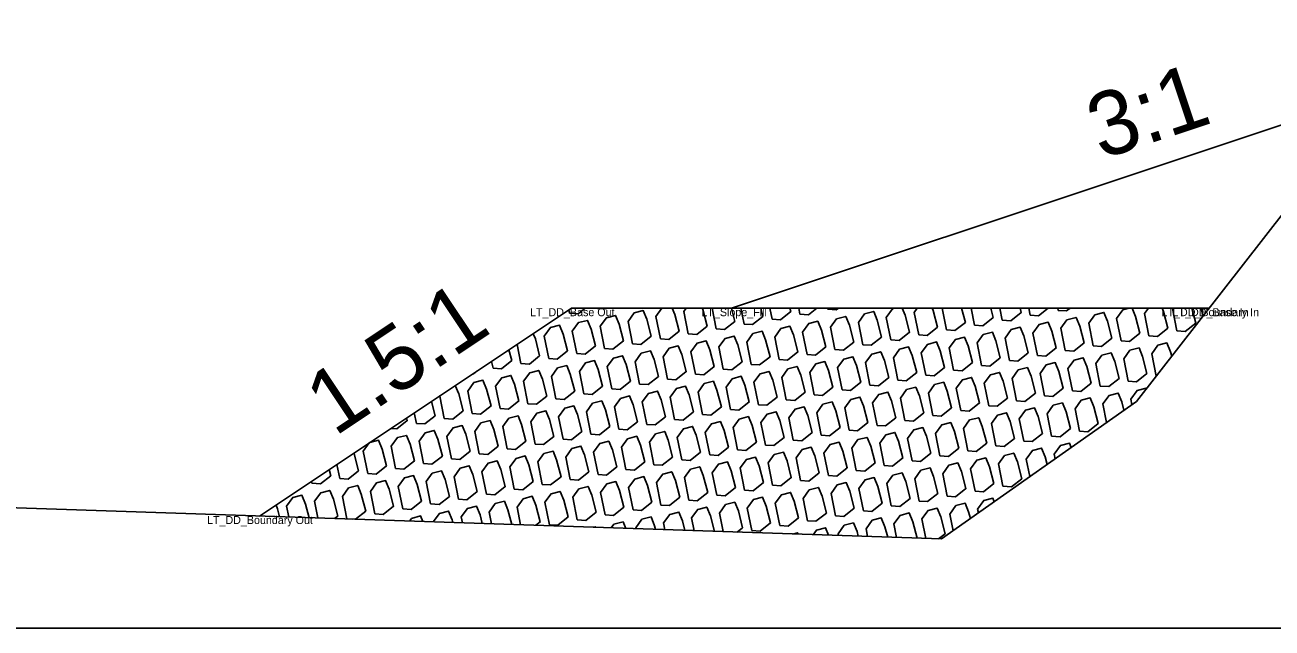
# Model space of a CAD drawing. Extents: x -26 to 203, y -10 to 20020.
# Drawn here: x 60.55 to 76.13, y 15500 to 15507.54 of the extents above; entities that cross this region are included whole.
import ezdxf

# ---------------------------------------------------------------- set-up
doc = ezdxf.new("R2010")
doc.units = 0
for name, color, linetype in [('Default', 7, 'Continuous'), ('Exist Cross Section Cell', 7, 'Continuous'), ('Exist XS Ground Line', 7, 'Continuous'), ('Old_Level_1', 7, 'Continuous'), ('Prop CMT Rip Rap Class II', 7, 'Continuous'), ('Prop CMT Slope Grass', 7, 'Continuous'), ('Prop XS Side Slope Text', 7, 'Continuous')]:
    doc.layers.add(name, color=color, linetype=linetype)

msp = doc.modelspace()

# ---------------------------------------------------------------- linework, layer by layer
at = {"layer": 'Exist Cross Section Cell'}
msp.add_line((0, 15500), (100, 15500), dxfattribs=at)
at = {"layer": 'Exist XS Ground Line'}
for p, q in [((74.431, 15502.834), (76.297, 15505.23)), ((71.996, 15501.114), (74.431, 15502.834)), ((57.187, 15501.614), (71.996, 15501.114))]:
    msp.add_line(p, q, dxfattribs=at)
at = {"layer": 'Old_Level_1'}
for p, q in [((67.341, 15503.979), (67.35, 15503.937)), ((67.698, 15504), (67.698, 15503.998)), ((69.13, 15504), (69.182, 15503.74)), ((69.491, 15504), (69.53, 15503.801)), ((69.852, 15504), (69.879, 15503.863)), ((70.212, 15504), (70.227, 15503.924)), ((70.573, 15504), (70.576, 15503.986)), ((72.005, 15504), (72.059, 15503.728)), ((72.366, 15504), (72.408, 15503.789)), ((72.727, 15504), (72.756, 15503.851)), ((73.088, 15504), (73.105, 15503.912)), ((73.448, 15504), (73.454, 15503.973)), ((75.241, 15504), (75.261, 15503.9)), ((66.694, 15503.548), (66.741, 15503.31)), ((66.376, 15503.335), (66.393, 15503.248)), ((65.41, 15502.691), (65.436, 15502.56)), ((64.444, 15502.047), (64.479, 15501.871)), ((64.125, 15501.835), (64.13, 15501.81)), ((63.478, 15501.403), (63.479, 15501.401)), ((64.568, 15501.367), (64.637, 15501.362))]:
    msp.add_line(p, q, dxfattribs=at)
for points in [[(67.35, 15503.937), (67.455, 15503.929), (67.544, 15504)], [(67.698, 15503.998), (67.804, 15503.99), (67.816, 15504)], [(68.503, 15504), (68.429, 15503.897), (68.484, 15503.617)], [(68.484, 15503.617), (68.59, 15503.609), (68.719, 15503.713), (68.665, 15503.923), (68.633, 15504)], [(68.807, 15504), (68.777, 15503.958), (68.833, 15503.678)], [(68.833, 15503.678), (68.938, 15503.671), (69.068, 15503.774), (69.013, 15503.985), (69.007, 15504)], [(69.182, 15503.74), (69.287, 15503.732), (69.416, 15503.835), (69.374, 15504)], [(69.53, 15503.801), (69.635, 15503.794), (69.765, 15503.897), (69.738, 15504)], [(69.879, 15503.863), (69.984, 15503.855), (70.114, 15503.958), (70.103, 15504)], [(70.227, 15503.924), (70.333, 15503.917), (70.437, 15504)], [(70.576, 15503.986), (70.681, 15503.978), (70.709, 15504)], [(71.418, 15504), (71.383, 15503.991), (71.306, 15503.885), (71.362, 15503.605)], [(71.362, 15503.605), (71.467, 15503.597), (71.597, 15503.7), (71.542, 15503.911), (71.506, 15504)], [(71.694, 15504), (71.655, 15503.946), (71.711, 15503.666)], [(71.711, 15503.666), (71.816, 15503.658), (71.945, 15503.762), (71.891, 15503.972), (71.88, 15504)], [(72.059, 15503.728), (72.164, 15503.72), (72.294, 15503.823), (72.248, 15504)], [(72.408, 15503.789), (72.513, 15503.781), (72.643, 15503.885), (72.613, 15504)], [(72.756, 15503.851), (72.862, 15503.843), (72.991, 15503.946), (72.977, 15504)], [(73.105, 15503.912), (73.21, 15503.904), (73.33, 15504)], [(73.454, 15503.973), (73.559, 15503.966), (73.602, 15504)], [(74.343, 15504), (74.261, 15503.979), (74.184, 15503.872), (74.24, 15503.592)], [(74.24, 15503.592), (74.345, 15503.585), (74.474, 15503.688), (74.42, 15503.898), (74.378, 15504)], [(74.581, 15504), (74.533, 15503.934), (74.588, 15503.654)], [(74.588, 15503.654), (74.694, 15503.646), (74.823, 15503.749), (74.769, 15503.96), (74.752, 15504)], [(74.885, 15504), (74.881, 15503.995), (74.937, 15503.715)], [(74.937, 15503.715), (75.042, 15503.708), (75.172, 15503.811), (75.123, 15504)], [(66.741, 15503.31), (66.847, 15503.302), (66.976, 15503.405), (66.922, 15503.616), (66.895, 15503.681)], [(74.872, 15503.401), (74.858, 15503.456), (74.812, 15503.566), (74.699, 15503.536), (74.622, 15503.43), (74.677, 15503.15)], [(66.393, 15503.248), (66.498, 15503.241), (66.628, 15503.344), (66.592, 15503.48)], [(66.142, 15503.18), (66.149, 15503.179), (66.19, 15503.212)], [(65.784, 15502.621), (65.89, 15502.614), (66.019, 15502.717), (65.965, 15502.927), (65.922, 15503.032)], [(74.276, 15502.725), (74.249, 15502.829), (74.204, 15502.939), (74.09, 15502.909), (74.013, 15502.803), (74.059, 15502.572)], [(74.555, 15502.994), (74.553, 15503), (74.439, 15502.971), (74.362, 15502.864), (74.375, 15502.795)], [(65.436, 15502.56), (65.541, 15502.552), (65.671, 15502.655), (65.624, 15502.834)], [(65.733, 15502.907), (65.729, 15502.901), (65.784, 15502.621)], [(65.117, 15502.496), (65.193, 15502.491), (65.322, 15502.594), (65.313, 15502.627)], [(64.847, 15502.316), (64.772, 15502.213), (64.828, 15501.933)], [(64.828, 15501.933), (64.933, 15501.925), (65.062, 15502.028), (65.008, 15502.239), (64.963, 15502.349), (64.853, 15502.32)], [(73.617, 15502.259), (73.596, 15502.312), (73.482, 15502.282), (73.405, 15502.176), (73.416, 15502.118)], [(64.479, 15501.871), (64.584, 15501.864), (64.714, 15501.967), (64.659, 15502.177), (64.655, 15502.188)], [(73.316, 15502.047), (73.292, 15502.14), (73.247, 15502.25), (73.133, 15502.221), (73.056, 15502.114), (73.1, 15501.894)], [(64.13, 15501.81), (64.236, 15501.802), (64.365, 15501.905), (64.345, 15501.982)], [(64.414, 15501.37), (64.454, 15501.401), (64.4, 15501.612), (64.354, 15501.722), (64.241, 15501.692), (64.164, 15501.586), (64.205, 15501.377)], [(64.675, 15501.361), (64.803, 15501.463), (64.748, 15501.673), (64.703, 15501.783), (64.589, 15501.754), (64.512, 15501.647), (64.568, 15501.367)], [(63.727, 15501.393), (63.702, 15501.489), (63.682, 15501.539)], [(64.095, 15501.38), (64.051, 15501.55), (64.006, 15501.66), (63.892, 15501.631), (63.815, 15501.524), (63.842, 15501.389)], [(66.259, 15501.307), (66.231, 15501.415), (66.186, 15501.525), (66.073, 15501.495), (65.996, 15501.389), (66.01, 15501.316)], [(66.627, 15501.295), (66.58, 15501.477), (66.535, 15501.586), (66.421, 15501.557), (66.344, 15501.45), (66.373, 15501.303)], [(66.929, 15501.285), (66.983, 15501.327), (66.929, 15501.538), (66.884, 15501.648), (66.77, 15501.618), (66.693, 15501.512), (66.737, 15501.291)], [(69.159, 15501.209), (69.109, 15501.403), (69.064, 15501.512), (68.95, 15501.483), (68.873, 15501.377), (68.905, 15501.218)], [(69.444, 15501.2), (69.512, 15501.254), (69.458, 15501.464), (69.413, 15501.574), (69.299, 15501.545), (69.222, 15501.438), (69.268, 15501.206)], [(72.357, 15501.369), (72.335, 15501.452), (72.29, 15501.562), (72.176, 15501.532), (72.099, 15501.426), (72.141, 15501.216)], [(72.656, 15501.58), (72.639, 15501.623), (72.525, 15501.594), (72.448, 15501.487), (72.457, 15501.44)], [(65.518, 15501.332), (65.489, 15501.402), (65.375, 15501.372), (65.35, 15501.338)], [(65.892, 15501.32), (65.883, 15501.354), (65.838, 15501.463), (65.724, 15501.434), (65.647, 15501.328)], [(68.424, 15501.234), (68.412, 15501.28), (68.367, 15501.39), (68.253, 15501.36), (68.176, 15501.254), (68.178, 15501.242)], [(68.791, 15501.222), (68.761, 15501.341), (68.715, 15501.451), (68.602, 15501.422), (68.525, 15501.315), (68.541, 15501.23)], [(71.324, 15501.136), (71.29, 15501.268), (71.244, 15501.377), (71.131, 15501.348), (71.054, 15501.241), (71.073, 15501.145)], [(71.691, 15501.124), (71.638, 15501.329), (71.593, 15501.439), (71.479, 15501.409), (71.402, 15501.303), (71.436, 15501.132)], [(71.959, 15501.115), (72.041, 15501.18), (71.987, 15501.39), (71.942, 15501.5), (71.828, 15501.471), (71.751, 15501.364), (71.799, 15501.12)], [(67.672, 15501.26), (67.67, 15501.267), (67.646, 15501.26)], [(68.052, 15501.247), (68.018, 15501.328), (67.904, 15501.299), (67.871, 15501.253)], [(70.586, 15501.161), (70.547, 15501.254), (70.433, 15501.225), (70.392, 15501.168)], [(70.956, 15501.149), (70.941, 15501.206), (70.896, 15501.316), (70.782, 15501.286), (70.705, 15501.18), (70.71, 15501.157)], [(70.206, 15501.174), (70.199, 15501.193), (70.135, 15501.176)]]:
    msp.add_lwpolyline(points, dxfattribs=at)
for points in [[(67.439, 15503.433), (67.544, 15503.425), (67.673, 15503.528), (67.619, 15503.739), (67.574, 15503.848), (67.46, 15503.819), (67.383, 15503.713)], [(67.787, 15503.494), (67.892, 15503.486), (68.022, 15503.59), (67.968, 15503.8), (67.922, 15503.91), (67.809, 15503.88), (67.732, 15503.774)], [(68.136, 15503.556), (68.241, 15503.548), (68.371, 15503.651), (68.316, 15503.862), (68.271, 15503.971), (68.157, 15503.942), (68.08, 15503.835)], [(70.665, 15503.482), (70.77, 15503.474), (70.9, 15503.577), (70.845, 15503.788), (70.8, 15503.898), (70.686, 15503.868), (70.609, 15503.762)], [(71.013, 15503.543), (71.119, 15503.536), (71.248, 15503.639), (71.194, 15503.849), (71.149, 15503.959), (71.035, 15503.93), (70.958, 15503.823)], [(73.542, 15503.469), (73.648, 15503.462), (73.777, 15503.565), (73.723, 15503.776), (73.678, 15503.885), (73.564, 15503.856), (73.487, 15503.749)], [(73.891, 15503.531), (73.996, 15503.523), (74.126, 15503.626), (74.071, 15503.837), (74.026, 15503.947), (73.913, 15503.917), (73.835, 15503.811)], [(67.09, 15503.371), (67.195, 15503.363), (67.325, 15503.467), (67.27, 15503.677), (67.225, 15503.787), (67.111, 15503.758), (67.034, 15503.651)], [(69.619, 15503.297), (69.724, 15503.29), (69.854, 15503.393), (69.799, 15503.603), (69.754, 15503.713), (69.64, 15503.684), (69.563, 15503.577)], [(69.968, 15503.359), (70.073, 15503.351), (70.202, 15503.454), (70.148, 15503.665), (70.103, 15503.775), (69.989, 15503.745), (69.912, 15503.639)], [(70.316, 15503.42), (70.421, 15503.413), (70.551, 15503.516), (70.497, 15503.726), (70.451, 15503.836), (70.338, 15503.807), (70.261, 15503.7)], [(72.497, 15503.285), (72.602, 15503.277), (72.731, 15503.381), (72.677, 15503.591), (72.632, 15503.701), (72.518, 15503.671), (72.441, 15503.565)], [(72.845, 15503.346), (72.951, 15503.339), (73.08, 15503.442), (73.026, 15503.653), (72.98, 15503.762), (72.867, 15503.733), (72.79, 15503.626)], [(73.194, 15503.408), (73.299, 15503.4), (73.429, 15503.503), (73.374, 15503.714), (73.329, 15503.824), (73.215, 15503.794), (73.138, 15503.688)], [(68.922, 15503.174), (69.027, 15503.167), (69.157, 15503.27), (69.102, 15503.481), (69.057, 15503.59), (68.943, 15503.561), (68.866, 15503.454)], [(69.27, 15503.236), (69.376, 15503.228), (69.505, 15503.331), (69.451, 15503.542), (69.406, 15503.652), (69.292, 15503.622), (69.215, 15503.516)], [(71.799, 15503.162), (71.905, 15503.154), (72.034, 15503.258), (71.98, 15503.468), (71.935, 15503.578), (71.821, 15503.548), (71.744, 15503.442)], [(72.148, 15503.224), (72.253, 15503.216), (72.383, 15503.319), (72.328, 15503.53), (72.283, 15503.639), (72.17, 15503.61), (72.092, 15503.503)], [(67.876, 15502.99), (67.981, 15502.982), (68.111, 15503.086), (68.056, 15503.296), (68.011, 15503.406), (67.898, 15503.376), (67.82, 15503.27)], [(68.225, 15503.051), (68.33, 15503.044), (68.459, 15503.147), (68.405, 15503.358), (68.36, 15503.467), (68.246, 15503.438), (68.169, 15503.331)], [(68.573, 15503.113), (68.679, 15503.105), (68.808, 15503.208), (68.754, 15503.419), (68.708, 15503.529), (68.595, 15503.499), (68.518, 15503.393)], [(70.754, 15502.978), (70.859, 15502.97), (70.989, 15503.073), (70.934, 15503.284), (70.889, 15503.393), (70.775, 15503.364), (70.698, 15503.258)], [(71.102, 15503.039), (71.208, 15503.031), (71.337, 15503.135), (71.283, 15503.345), (71.238, 15503.455), (71.124, 15503.426), (71.047, 15503.319)], [(71.451, 15503.101), (71.556, 15503.093), (71.686, 15503.196), (71.631, 15503.407), (71.586, 15503.516), (71.472, 15503.487), (71.395, 15503.381)], [(73.631, 15502.965), (73.737, 15502.958), (73.866, 15503.061), (73.812, 15503.271), (73.767, 15503.381), (73.653, 15503.352), (73.576, 15503.245)], [(73.98, 15503.027), (74.085, 15503.019), (74.215, 15503.122), (74.16, 15503.333), (74.115, 15503.443), (74.001, 15503.413), (73.924, 15503.307)], [(74.329, 15503.088), (74.434, 15503.081), (74.563, 15503.184), (74.509, 15503.394), (74.464, 15503.504), (74.35, 15503.475), (74.273, 15503.368)], [(67.179, 15502.867), (67.284, 15502.859), (67.414, 15502.963), (67.359, 15503.173), (67.314, 15503.283), (67.2, 15503.253), (67.123, 15503.147)], [(67.527, 15502.928), (67.633, 15502.921), (67.762, 15503.024), (67.708, 15503.235), (67.663, 15503.344), (67.549, 15503.315), (67.472, 15503.208)], [(70.057, 15502.855), (70.162, 15502.847), (70.291, 15502.95), (70.237, 15503.161), (70.192, 15503.271), (70.078, 15503.241), (70.001, 15503.135)], [(70.405, 15502.916), (70.51, 15502.909), (70.64, 15503.012), (70.585, 15503.222), (70.54, 15503.332), (70.427, 15503.303), (70.35, 15503.196)], [(72.934, 15502.842), (73.039, 15502.835), (73.169, 15502.938), (73.115, 15503.149), (73.069, 15503.258), (72.956, 15503.229), (72.879, 15503.122)], [(73.283, 15502.904), (73.388, 15502.896), (73.518, 15502.999), (73.463, 15503.21), (73.418, 15503.32), (73.304, 15503.29), (73.227, 15503.184)], [(66.133, 15502.683), (66.238, 15502.675), (66.368, 15502.778), (66.313, 15502.989), (66.268, 15503.098), (66.155, 15503.069), (66.077, 15502.963)], [(66.482, 15502.744), (66.587, 15502.736), (66.716, 15502.84), (66.662, 15503.05), (66.617, 15503.16), (66.503, 15503.131), (66.426, 15503.024)], [(66.83, 15502.806), (66.936, 15502.798), (67.065, 15502.901), (67.011, 15503.112), (66.965, 15503.221), (66.852, 15503.192), (66.775, 15503.086)], [(69.011, 15502.67), (69.116, 15502.663), (69.246, 15502.766), (69.191, 15502.976), (69.146, 15503.086), (69.032, 15503.057), (68.955, 15502.95)], [(69.359, 15502.732), (69.465, 15502.724), (69.594, 15502.827), (69.54, 15503.038), (69.495, 15503.148), (69.381, 15503.118), (69.304, 15503.012)], [(69.708, 15502.793), (69.813, 15502.786), (69.943, 15502.889), (69.888, 15503.099), (69.843, 15503.209), (69.729, 15503.18), (69.652, 15503.073)], [(71.888, 15502.658), (71.994, 15502.65), (72.123, 15502.754), (72.069, 15502.964), (72.024, 15503.074), (71.91, 15503.044), (71.833, 15502.938)], [(72.237, 15502.719), (72.342, 15502.712), (72.472, 15502.815), (72.417, 15503.026), (72.372, 15503.135), (72.258, 15503.106), (72.181, 15502.999)], [(72.586, 15502.781), (72.691, 15502.773), (72.82, 15502.876), (72.766, 15503.087), (72.721, 15503.197), (72.607, 15503.167), (72.53, 15503.061)], [(68.314, 15502.547), (68.419, 15502.54), (68.548, 15502.643), (68.494, 15502.854), (68.449, 15502.963), (68.335, 15502.934), (68.258, 15502.827)], [(68.662, 15502.609), (68.767, 15502.601), (68.897, 15502.704), (68.842, 15502.915), (68.797, 15503.025), (68.684, 15502.995), (68.607, 15502.889)], [(71.191, 15502.535), (71.296, 15502.527), (71.426, 15502.631), (71.372, 15502.841), (71.326, 15502.951), (71.213, 15502.921), (71.136, 15502.815)], [(71.54, 15502.596), (71.645, 15502.589), (71.775, 15502.692), (71.72, 15502.903), (71.675, 15503.012), (71.561, 15502.983), (71.484, 15502.876)], [(67.268, 15502.363), (67.373, 15502.355), (67.503, 15502.459), (67.448, 15502.669), (67.403, 15502.779), (67.289, 15502.749), (67.212, 15502.643)], [(67.616, 15502.424), (67.722, 15502.417), (67.851, 15502.52), (67.797, 15502.731), (67.752, 15502.84), (67.638, 15502.811), (67.561, 15502.704)], [(67.965, 15502.486), (68.07, 15502.478), (68.2, 15502.581), (68.145, 15502.792), (68.1, 15502.902), (67.986, 15502.872), (67.909, 15502.766)], [(70.145, 15502.351), (70.251, 15502.343), (70.38, 15502.446), (70.326, 15502.657), (70.281, 15502.766), (70.167, 15502.737), (70.09, 15502.631)], [(70.494, 15502.412), (70.599, 15502.404), (70.729, 15502.508), (70.674, 15502.718), (70.629, 15502.828), (70.515, 15502.799), (70.438, 15502.692)], [(70.843, 15502.474), (70.948, 15502.466), (71.077, 15502.569), (71.023, 15502.78), (70.978, 15502.889), (70.864, 15502.86), (70.787, 15502.754)], [(73.372, 15502.4), (73.477, 15502.392), (73.606, 15502.495), (73.552, 15502.706), (73.507, 15502.816), (73.393, 15502.786), (73.316, 15502.68)], [(73.72, 15502.461), (73.826, 15502.454), (73.955, 15502.557), (73.901, 15502.767), (73.855, 15502.877), (73.742, 15502.848), (73.665, 15502.741)], [(66.571, 15502.24), (66.676, 15502.232), (66.805, 15502.336), (66.751, 15502.546), (66.706, 15502.656), (66.592, 15502.626), (66.515, 15502.52)], [(66.919, 15502.301), (67.024, 15502.294), (67.154, 15502.397), (67.1, 15502.608), (67.054, 15502.717), (66.941, 15502.688), (66.864, 15502.581)], [(69.448, 15502.228), (69.553, 15502.22), (69.683, 15502.323), (69.629, 15502.534), (69.583, 15502.644), (69.47, 15502.614), (69.393, 15502.508)], [(69.797, 15502.289), (69.902, 15502.282), (70.032, 15502.385), (69.977, 15502.595), (69.932, 15502.705), (69.818, 15502.676), (69.741, 15502.569)], [(72.326, 15502.215), (72.431, 15502.208), (72.561, 15502.311), (72.506, 15502.522), (72.461, 15502.631), (72.347, 15502.602), (72.27, 15502.495)], [(72.674, 15502.277), (72.78, 15502.269), (72.909, 15502.372), (72.855, 15502.583), (72.81, 15502.693), (72.696, 15502.663), (72.619, 15502.557)], [(73.023, 15502.338), (73.128, 15502.331), (73.258, 15502.434), (73.203, 15502.644), (73.158, 15502.754), (73.045, 15502.725), (72.967, 15502.618)], [(65.525, 15502.056), (65.63, 15502.048), (65.76, 15502.151), (65.705, 15502.362), (65.66, 15502.471), (65.546, 15502.442), (65.469, 15502.336)], [(65.873, 15502.117), (65.979, 15502.109), (66.108, 15502.213), (66.054, 15502.423), (66.009, 15502.533), (65.895, 15502.504), (65.818, 15502.397)], [(66.222, 15502.179), (66.327, 15502.171), (66.457, 15502.274), (66.402, 15502.485), (66.357, 15502.594), (66.243, 15502.565), (66.166, 15502.459)], [(68.402, 15502.043), (68.508, 15502.036), (68.637, 15502.139), (68.583, 15502.349), (68.538, 15502.459), (68.424, 15502.43), (68.347, 15502.323)], [(68.751, 15502.105), (68.856, 15502.097), (68.986, 15502.2), (68.931, 15502.411), (68.886, 15502.521), (68.772, 15502.491), (68.695, 15502.385)], [(69.1, 15502.166), (69.205, 15502.159), (69.334, 15502.262), (69.28, 15502.472), (69.235, 15502.582), (69.121, 15502.553), (69.044, 15502.446)], [(71.28, 15502.031), (71.385, 15502.023), (71.515, 15502.127), (71.46, 15502.337), (71.415, 15502.447), (71.302, 15502.417), (71.224, 15502.311)], [(71.629, 15502.092), (71.734, 15502.085), (71.863, 15502.188), (71.809, 15502.399), (71.764, 15502.508), (71.65, 15502.479), (71.573, 15502.372)], [(71.977, 15502.154), (72.083, 15502.146), (72.212, 15502.249), (72.158, 15502.46), (72.112, 15502.57), (71.999, 15502.54), (71.922, 15502.434)], [(65.176, 15501.994), (65.281, 15501.987), (65.411, 15502.09), (65.357, 15502.3), (65.311, 15502.41), (65.198, 15502.381), (65.121, 15502.274)], [(67.705, 15501.92), (67.81, 15501.913), (67.94, 15502.016), (67.886, 15502.227), (67.84, 15502.336), (67.727, 15502.307), (67.65, 15502.2)], [(68.054, 15501.982), (68.159, 15501.974), (68.289, 15502.077), (68.234, 15502.288), (68.189, 15502.398), (68.075, 15502.368), (67.998, 15502.262)], [(70.583, 15501.908), (70.688, 15501.9), (70.818, 15502.004), (70.763, 15502.214), (70.718, 15502.324), (70.604, 15502.294), (70.527, 15502.188)], [(70.931, 15501.969), (71.037, 15501.962), (71.166, 15502.065), (71.112, 15502.276), (71.067, 15502.385), (70.953, 15502.356), (70.876, 15502.249)], [(66.659, 15501.736), (66.765, 15501.728), (66.894, 15501.832), (66.84, 15502.042), (66.795, 15502.152), (66.681, 15502.122), (66.604, 15502.016)], [(67.008, 15501.797), (67.113, 15501.79), (67.243, 15501.893), (67.188, 15502.104), (67.143, 15502.213), (67.029, 15502.184), (66.952, 15502.077)], [(67.357, 15501.859), (67.462, 15501.851), (67.591, 15501.954), (67.537, 15502.165), (67.492, 15502.275), (67.378, 15502.245), (67.301, 15502.139)], [(69.537, 15501.724), (69.642, 15501.716), (69.772, 15501.819), (69.717, 15502.03), (69.672, 15502.139), (69.559, 15502.11), (69.481, 15502.004)], [(69.886, 15501.785), (69.991, 15501.777), (70.12, 15501.881), (70.066, 15502.091), (70.021, 15502.201), (69.907, 15502.172), (69.83, 15502.065)], [(70.234, 15501.847), (70.34, 15501.839), (70.469, 15501.942), (70.415, 15502.153), (70.369, 15502.262), (70.256, 15502.233), (70.179, 15502.127)], [(72.763, 15501.773), (72.869, 15501.765), (72.998, 15501.868), (72.944, 15502.079), (72.899, 15502.189), (72.785, 15502.159), (72.708, 15502.053)], [(65.962, 15501.613), (66.067, 15501.605), (66.197, 15501.709), (66.143, 15501.919), (66.097, 15502.029), (65.984, 15501.999), (65.907, 15501.893)], [(66.311, 15501.674), (66.416, 15501.667), (66.546, 15501.77), (66.491, 15501.981), (66.446, 15502.09), (66.332, 15502.061), (66.255, 15501.954)], [(68.84, 15501.601), (68.945, 15501.593), (69.075, 15501.696), (69.02, 15501.907), (68.975, 15502.017), (68.861, 15501.987), (68.784, 15501.881)], [(69.188, 15501.662), (69.294, 15501.655), (69.423, 15501.758), (69.369, 15501.968), (69.324, 15502.078), (69.21, 15502.049), (69.133, 15501.942)], [(71.718, 15501.588), (71.823, 15501.581), (71.952, 15501.684), (71.898, 15501.895), (71.853, 15502.004), (71.739, 15501.975), (71.662, 15501.868)], [(72.066, 15501.65), (72.171, 15501.642), (72.301, 15501.745), (72.246, 15501.956), (72.201, 15502.066), (72.088, 15502.036), (72.011, 15501.93)], [(72.415, 15501.711), (72.52, 15501.704), (72.65, 15501.807), (72.595, 15502.017), (72.55, 15502.127), (72.436, 15502.098), (72.359, 15501.991)], [(64.916, 15501.429), (65.022, 15501.421), (65.151, 15501.524), (65.097, 15501.735), (65.052, 15501.844), (64.938, 15501.815), (64.861, 15501.709)], [(65.265, 15501.49), (65.37, 15501.482), (65.5, 15501.586), (65.445, 15501.796), (65.4, 15501.906), (65.286, 15501.877), (65.209, 15501.77)], [(65.614, 15501.552), (65.719, 15501.544), (65.848, 15501.647), (65.794, 15501.858), (65.749, 15501.967), (65.635, 15501.938), (65.558, 15501.832)], [(67.794, 15501.416), (67.899, 15501.409), (68.029, 15501.512), (67.974, 15501.722), (67.929, 15501.832), (67.816, 15501.803), (67.738, 15501.696)], [(68.143, 15501.478), (68.248, 15501.47), (68.377, 15501.573), (68.323, 15501.784), (68.278, 15501.894), (68.164, 15501.864), (68.087, 15501.758)], [(68.491, 15501.539), (68.597, 15501.532), (68.726, 15501.635), (68.672, 15501.845), (68.627, 15501.955), (68.513, 15501.926), (68.436, 15501.819)], [(71.02, 15501.465), (71.126, 15501.458), (71.255, 15501.561), (71.201, 15501.772), (71.156, 15501.881), (71.042, 15501.852), (70.965, 15501.745)], [(71.369, 15501.527), (71.474, 15501.519), (71.604, 15501.622), (71.549, 15501.833), (71.504, 15501.943), (71.39, 15501.913), (71.313, 15501.807)], [(67.097, 15501.293), (67.202, 15501.286), (67.332, 15501.389), (67.277, 15501.6), (67.232, 15501.709), (67.118, 15501.68), (67.041, 15501.573)], [(67.446, 15501.355), (67.551, 15501.347), (67.68, 15501.45), (67.626, 15501.661), (67.581, 15501.771), (67.467, 15501.741), (67.39, 15501.635)], [(69.975, 15501.281), (70.08, 15501.273), (70.209, 15501.377), (70.155, 15501.587), (70.11, 15501.697), (69.996, 15501.667), (69.919, 15501.561)], [(70.323, 15501.342), (70.428, 15501.335), (70.558, 15501.438), (70.504, 15501.649), (70.458, 15501.758), (70.345, 15501.729), (70.268, 15501.622)], [(70.672, 15501.404), (70.777, 15501.396), (70.907, 15501.5), (70.852, 15501.71), (70.807, 15501.82), (70.693, 15501.79), (70.616, 15501.684)], [(69.626, 15501.22), (69.731, 15501.212), (69.861, 15501.315), (69.806, 15501.526), (69.761, 15501.635), (69.647, 15501.606), (69.57, 15501.5)]]:
    msp.add_lwpolyline(points, close=True, dxfattribs=at)
at = {"layer": 'Prop CMT Rip Rap Class II'}
for points in [[(75.339, 15504), (67.373, 15504), (63.475, 15501.401)], [(75.339, 15504), (75.339, 15504)]]:
    msp.add_lwpolyline(points, dxfattribs=at)
at = {"layer": 'Prop CMT Slope Grass'}
msp.add_lwpolyline([(80, 15507.542), (69.373, 15504)], dxfattribs=at)

# ---------------------------------------------------------------- texts
at = {"layer": 'Default'}
for s, p in [('LT_DD_Base Out', (66.856, 15503.9)), ('LT_Slope_Fill', (68.997, 15503.9)), ('LT_DD_Boundary In', (74.745, 15503.9)), ('LT_DD_Base In', (74.883, 15503.9)), ('LT_DD_Boundary Out', (62.82, 15501.301))]:
    msp.add_text(s, height=0.1, dxfattribs=at).set_placement(p)
at = {"layer": 'Prop XS Side Slope Text'}
for s, rotation, p in [('3:1', 18.4332, (73.99, 15505.855)), ('1.5:1', 33.6914, (64.415, 15502.388))]:
    msp.add_text(s, height=0.8, rotation=rotation, dxfattribs=at).set_placement(p)

doc.saveas('drawing.dxf')
